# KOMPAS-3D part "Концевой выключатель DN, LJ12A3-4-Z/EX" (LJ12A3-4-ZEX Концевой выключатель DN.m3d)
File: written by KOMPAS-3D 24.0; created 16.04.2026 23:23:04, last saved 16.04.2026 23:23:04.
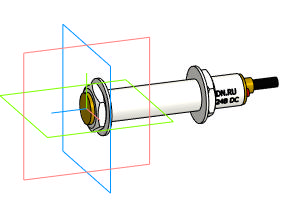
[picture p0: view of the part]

Document properties: Автор: DN.RU; Полное имя файла: D:\PROJECT CAD\DN.RU\...200(ACTUALE). Концевой выключатель DN.ru\Исходники\LJ12A3-4-ZEX\LJ12A3-4-ZEX Концевой выключатель DN.m3d

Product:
- Body: Твердое тело1  | qty 1
    Масса: 0.068115
- Part/product: Концевой выключатель DN  | designation LJ12A3-4-Z/EX
    Масса: 0.05
    Раздел спецификации: Прочие изделия
    Комментарий: D290-00327
    Примечание: D290-00327
    additional columns: Типовые

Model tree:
1. Твердое тело1  (labels: Твердое тело1)

Expressions: LJ12A3-4-Z/EX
